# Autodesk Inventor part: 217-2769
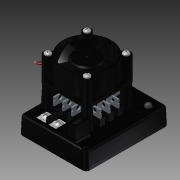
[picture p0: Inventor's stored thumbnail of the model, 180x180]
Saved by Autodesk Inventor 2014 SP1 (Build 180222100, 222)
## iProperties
Category: Control System
Company: Autodesk, Inc.
Created: 2012-12
Part Number: 217-2769
Document SubType Name: Modeling
Density: 1.74475 g/cm^3
Project: FIRST
Catalog Web Link: http://www.vexrobotics.com/vexpro/motor-controllers/217-2769.html
Description: Speed Controller, Victor 888
Vendor: Innovation First, Inc.
Mass: 99.7903 g
Surface Area: 516.876 cm^2
Volume: 57.1945 cm^3
Material: Generic
Appearance: Default
Title: Speed Controller, Victor 888
Author: Autodesk, Inc.
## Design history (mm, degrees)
derived "FR-VIC884.iam"
body "Solid1"
node "FR-VIC884_1.ipt:1"
node "FR-VIC884_2.ipt:1"
node "KDE1204PKBX-8.iam:1::KDE1204PKBX-8_1.ipt:1"
node "KDE1204PKBX-8.iam:1::KDE1204PKBX-8_2.ipt:1"
node "KDE1204PKBX-8.iam:1::KDE1204PKBX-8_3.ipt:1"
node "KDE1204PKBX-8.iam:1::KDE1204PKBX-8_4.ipt:1"
node "FR-VIC884_3.ipt:1"
node "FR-VIC884_4.ipt:1"
node "FR-VIC884_5.ipt:1"
node "FR-VIC884_6.ipt:1"
node "FR-VIC884_6.ipt:3"
node "FR-VIC884_6.ipt:4"
node "FR-VIC884_6.ipt:5"
node "FR-VIC884_6.ipt:6"
node "FR-VIC884_6.ipt:7"
node "FR-VIC884_6.ipt:8"
node "FR-VIC884_6.ipt:9"
node "FR-VIC884_6.ipt:10"
node "FR-VIC884_6.ipt:11"
node "FR-VIC884_6.ipt:12"
node "FR-VIC884_6.ipt:13"
node "FR-VIC884_7.ipt:1"
node "FR-VIC884_7.ipt:2"
node "FR-VIC884_7.ipt:3"
node "FR-VIC884_7.ipt:4"
node "Cross Recessed Fillister Head Machine Screw - Type I - Inch "
node "Cross Recessed Fillister Head Machine Screw - Type I - Inch "
node "Cross Recessed Fillister Head Machine Screw - Type I - Inch "
node "Cross Recessed Fillister Head Machine Screw - Type I - Inch "
node "FR-VIC884.iam_Bodies"
